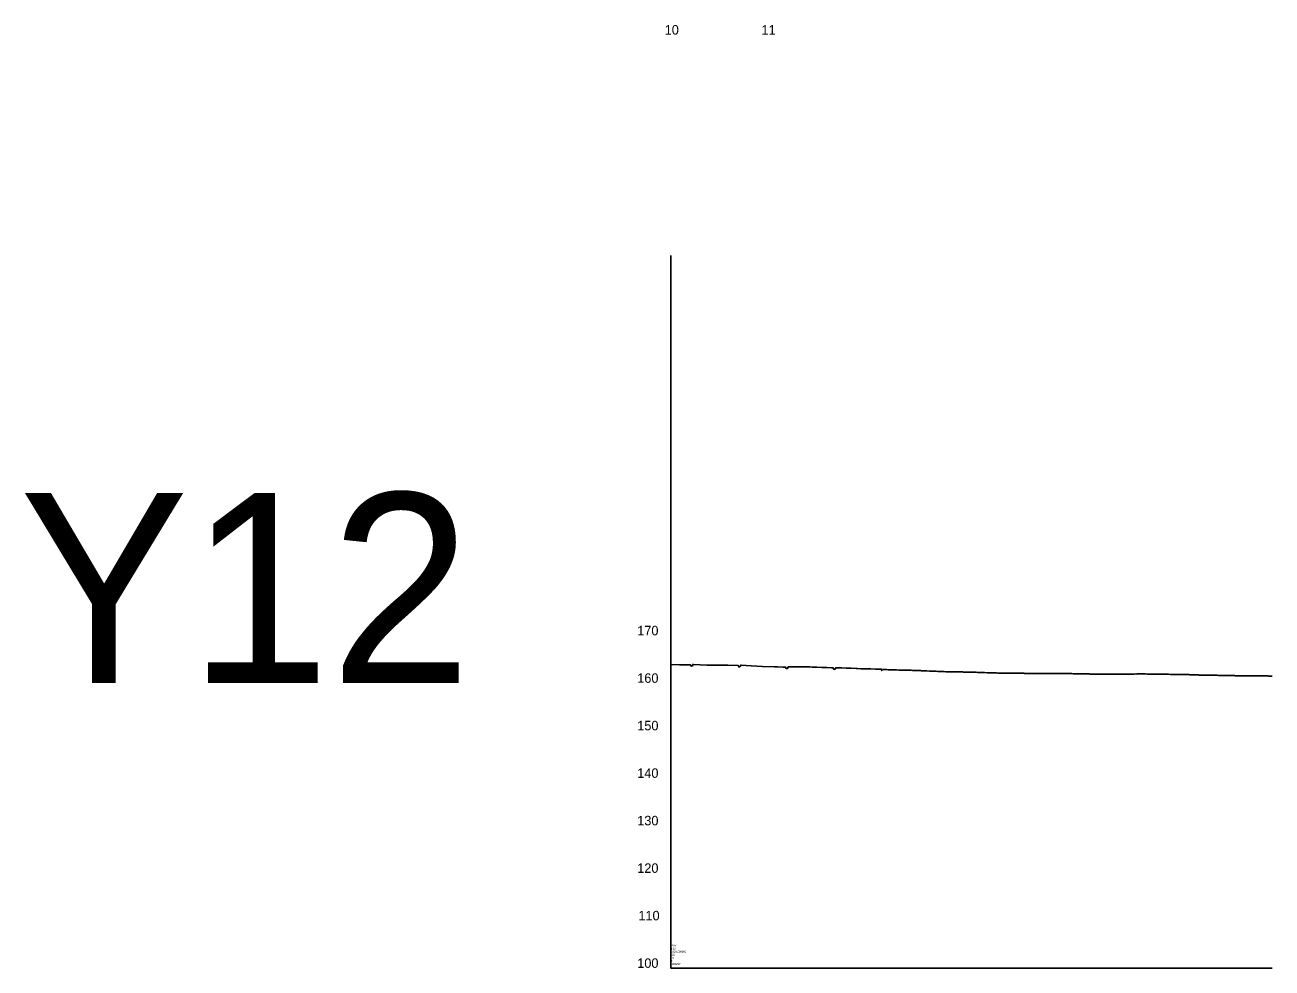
# Model space of a CAD drawing. Extents: x 1778432 to 1784301, y 601022 to 621789.
# Drawn here: x 1779463 to 1780776, y 606039 to 607032 of the extents above; entities that cross this region are included whole.
import ezdxf

# ---------------------------------------------------------------- set-up
doc = ezdxf.new("R2010")
doc.units = 0
for name, color, linetype in [('Exist Profile Cell', 7, 'Continuous'), ('Exist Vertical Profile Ground Line', 7, 'Continuous'), ('Exist Vertical Profile Horizontal Axis Label Major', 7, 'Continuous'), ('Exist Vertical Profile Vertical Axis Label', 7, 'Continuous'), ('Prop PFL Text', 7, 'Continuous')]:
    doc.layers.add(name, color=color, linetype=linetype)

msp = doc.modelspace()

# ---------------------------------------------------------------- linework, layer by layer
at = {"layer": 'Exist Profile Cell'}
for q in [(1780143, 606789.2), (1780775.8, 606039.2), (1780143, 606039.2)]:
    msp.add_line((1780143, 606039.2), q, dxfattribs=at)
at = {"layer": 'Exist Vertical Profile Ground Line'}
msp.add_lwpolyline([(1780143, 606358.7), (1780152.2, 606358.4), (1780163.8, 606358.3), (1780164.4, 606356.8), (1780165.2, 606357.2), (1780165.8, 606357.4), (1780166.4, 606359), (1780166.8, 606358.7), (1780180.8, 606358.1), (1780189.9, 606358), (1780202.9, 606358), (1780213.9, 606357.6), (1780214.5, 606356.1), (1780215.4, 606356.4), (1780215.9, 606356.5), (1780216.5, 606358), (1780216.9, 606358), (1780227.4, 606357.4), (1780239.5, 606356.7), (1780252.2, 606356.2), (1780255.6, 606356.1), (1780260.7, 606355.9), (1780263.8, 606355.9), (1780264.4, 606354.4), (1780265, 606354.4), (1780265.9, 606354.6), (1780266.5, 606356.1), (1780267, 606356.1), (1780271, 606356.1), (1780276.1, 606356.1), (1780277.8, 606356.1), (1780281.3, 606356.1), (1780286.4, 606356.1), (1780289.3, 606356.1), (1780291.6, 606356), (1780296.7, 606355.8), (1780301.9, 606355.6), (1780307, 606355.4), (1780312.2, 606355.2), (1780313.9, 606355.1), (1780314.5, 606353.6), (1780315.3, 606353.7), (1780315.9, 606353.8), (1780316.5, 606355.3), (1780316.9, 606355.3), (1780317.3, 606355.3), (1780322.5, 606355.1), (1780327.6, 606354.9), (1780329.5, 606354.9), (1780332.8, 606354.7), (1780337.9, 606354.5), (1780339.5, 606354.4), (1780343.1, 606354.3), (1780348.2, 606354.2), (1780352.5, 606354), (1780353.4, 606354), (1780358.5, 606353.9), (1780363.7, 606353.8), (1780364.4, 606353.8), (1780365, 606352.3), (1780366, 606353.5), (1780368.2, 606353.4), (1780368.9, 606353.4), (1780370, 606353.3), (1780371.8, 606353.2), (1780373, 606353.2), (1780374, 606353.1), (1780374.8, 606353.1), (1780377.3, 606353), (1780377.9, 606353), (1780379.1, 606353), (1780380.6, 606353), (1780382.8, 606352.9), (1780383.5, 606352.9), (1780384.5, 606352.9), (1780386.4, 606352.9), (1780387.7, 606352.8), (1780389.4, 606352.8), (1780391.6, 606352.7), (1780392.2, 606352.7), (1780392.6, 606352.7), (1780394.2, 606352.7), (1780394.6, 606352.7), (1780395.1, 606352.7), (1780396, 606352.6), (1780397.5, 606352.5), (1780398, 606352.5), (1780398.8, 606352.5), (1780399.7, 606352.5), (1780400.9, 606352.4), (1780401.5, 606352.4), (1780402.5, 606352.4), (1780403.8, 606352.4), (1780404.9, 606352.3), (1780405.7, 606352.3), (1780406.7, 606352.2), (1780407.4, 606352.2), (1780409.6, 606352.1), (1780410, 606352.1), (1780410.6, 606352.1), (1780412.6, 606351.9), (1780415.4, 606351.8), (1780416.1, 606351.7), (1780417.3, 606351.7), (1780418.3, 606351.7), (1780419.6, 606351.6), (1780420.3, 606351.6), (1780421.2, 606351.5), (1780422.3, 606351.5), (1780424, 606351.4), (1780425.5, 606351.3), (1780427.4, 606351.3), (1780429.8, 606351.2), (1780430.6, 606351.2), (1780432.4, 606351.1), (1780432.7, 606351.1), (1780434.4, 606351), (1780435.8, 606351), (1780436.2, 606351), (1780437.4, 606351), (1780438.1, 606351), (1780438.5, 606351), (1780439.9, 606350.9), (1780440.9, 606350.9), (1780441.3, 606350.9), (1780441.8, 606350.8), (1780442.4, 606350.9), (1780444.2, 606350.9), (1780445.4, 606350.8), (1780446.1, 606350.8), (1780447.5, 606350.8), (1780450, 606350.8), (1780450.9, 606350.7), (1780451.2, 606350.7), (1780452.9, 606350.7), (1780454.6, 606350.7), (1780455.7, 606350.6), (1780456.4, 606350.6), (1780457.7, 606350.6), (1780458.6, 606350.6), (1780460.1, 606350.6), (1780461.5, 606350.5), (1780462.7, 606350.5), (1780463.7, 606350.5), (1780464.3, 606350.5), (1780465.6, 606350.4), (1780466.7, 606350.3), (1780467.2, 606350.3), (1780467.9, 606350.3), (1780469.3, 606350.3), (1780470, 606350.2), (1780471.8, 606350.2), (1780473, 606350.1), (1780475.8, 606350), (1780477, 606350), (1780478.1, 606350), (1780478.6, 606350), (1780480.3, 606349.9), (1780481.5, 606349.9), (1780482.1, 606349.9), (1780483.3, 606349.8), (1780484.3, 606349.8), (1780485.6, 606349.8), (1780487.3, 606349.7), (1780488.5, 606349.7), (1780490.1, 606349.7), (1780492, 606349.6), (1780492.4, 606349.6), (1780493.2, 606349.6), (1780493.7, 606349.6), (1780495, 606349.6), (1780495.8, 606349.6), (1780497.6, 606349.6), (1780498.9, 606349.5), (1780500.5, 606349.5), (1780501.5, 606349.5), (1780502.7, 606349.5), (1780504.3, 606349.5), (1780506.1, 606349.4), (1780507.1, 606349.4), (1780507.9, 606349.4), (1780509.3, 606349.4), (1780510, 606349.4), (1780511.6, 606349.4), (1780513, 606349.4), (1780514.1, 606349.4), (1780514.6, 606349.4), (1780515.3, 606349.3), (1780515.7, 606349.3), (1780516.4, 606349.3), (1780517.6, 606349.3), (1780518.2, 606349.3), (1780518.8, 606349.3), (1780519.8, 606349.3), (1780520.8, 606349.3), (1780521.6, 606349.3), (1780523.3, 606349.3), (1780524.2, 606349.3), (1780525, 606349.3), (1780527, 606349.3), (1780528.4, 606349.3), (1780529.8, 606349.3), (1780530.4, 606349.3), (1780532.7, 606349.3), (1780533.6, 606349.3), (1780535.7, 606349.3), (1780537.4, 606349.3), (1780538.4, 606349.3), (1780538.8, 606349.3), (1780541.4, 606349.2), (1780542.5, 606349.2), (1780544.1, 606349.2), (1780545.2, 606349.2), (1780546.4, 606349.2), (1780546.9, 606349.2), (1780548.4, 606349.2), (1780549.5, 606349.1), (1780550, 606349.1), (1780550.5, 606349.1), (1780551.8, 606349.2), (1780552.5, 606349.2), (1780553.8, 606349.1), (1780555, 606349.1), (1780555.5, 606349.1), (1780556.3, 606349.1), (1780557.2, 606349.1), (1780557.8, 606349.1), (1780558.2, 606349.1), (1780559.6, 606349.1), (1780560.9, 606349.1), (1780561.3, 606349.1), (1780561.7, 606349.1), (1780562.6, 606349.1), (1780563.4, 606349.1), (1780563.8, 606349.1), (1780565.1, 606349.1), (1780566.3, 606349), (1780567.1, 606349), (1780568.1, 606349), (1780569, 606349), (1780569.4, 606349), (1780570.1, 606348.9), (1780571.8, 606348.9), (1780572.6, 606348.9), (1780573.6, 606348.9), (1780575, 606348.8), (1780575.6, 606348.8), (1780576.4, 606348.8), (1780577.4, 606348.8), (1780578, 606348.8), (1780579.2, 606348.8), (1780580.1, 606348.8), (1780580.6, 606348.7), (1780582, 606348.7), (1780583.5, 606348.7), (1780584.1, 606348.6), (1780584.7, 606348.6), (1780586.2, 606348.6), (1780587.7, 606348.6), (1780588.9, 606348.6), (1780589.6, 606348.6), (1780590.4, 606348.6), (1780591.4, 606348.6), (1780591.8, 606348.6), (1780593.1, 606348.5), (1780594.7, 606348.5), (1780595.4, 606348.5), (1780596, 606348.5), (1780596.9, 606348.5), (1780597.3, 606348.5), (1780599, 606348.5), (1780600.1, 606348.4), (1780600.8, 606348.4), (1780601.7, 606348.4), (1780602.9, 606348.4), (1780604, 606348.4), (1780605.5, 606348.4), (1780606.5, 606348.4), (1780607.5, 606348.4), (1780608.4, 606348.4), (1780609.4, 606348.4), (1780610.3, 606348.4), (1780610.7, 606348.4), (1780611.5, 606348.4), (1780613.2, 606348.4), (1780614, 606348.4), (1780615.6, 606348.4), (1780616.9, 606348.4), (1780617.8, 606348.5), (1780619, 606348.5), (1780619.5, 606348.5), (1780621.2, 606348.5), (1780621.5, 606348.5), (1780622.5, 606348.5), (1780623.6, 606348.5), (1780625.3, 606348.5), (1780627.8, 606348.6), (1780629.1, 606348.6), (1780630.7, 606348.6), (1780632.5, 606348.7), (1780632.8, 606348.7), (1780633.3, 606348.6), (1780634.3, 606348.7), (1780636, 606348.7), (1780636.7, 606348.7), (1780638.9, 606348.7), (1780639.3, 606348.7), (1780640.4, 606348.7), (1780641.2, 606348.7), (1780641.7, 606348.7), (1780642.6, 606348.7), (1780644.4, 606348.6), (1780645.9, 606348.6), (1780647.1, 606348.6), (1780647.9, 606348.6), (1780648.6, 606348.6), (1780649.9, 606348.6), (1780651.2, 606348.5), (1780651.7, 606348.5), (1780652.4, 606348.5), (1780653.4, 606348.5), (1780654.7, 606348.5), (1780655.4, 606348.5), (1780655.9, 606348.4), (1780657.7, 606348.4), (1780658.1, 606348.4), (1780659.2, 606348.4), (1780660.9, 606348.4), (1780662.9, 606348.4), (1780663.5, 606348.4), (1780664.6, 606348.4), (1780666.2, 606348.4), (1780667, 606348.4), (1780669, 606348.3), (1780670, 606348.3), (1780670.5, 606348.3), (1780671.5, 606348.3), (1780672, 606348.3), (1780673.1, 606348.3), (1780674.5, 606348.3), (1780676.2, 606348.2), (1780677.4, 606348.2), (1780678.3, 606348.2), (1780679.4, 606348.2), (1780679.9, 606348.2), (1780680.4, 606348.2), (1780681.8, 606348.1), (1780682.7, 606348.1), (1780683.7, 606348.1), (1780685.6, 606348.1), (1780687.4, 606348), (1780688.1, 606348), (1780689.3, 606347.9), (1780690.7, 606347.9), (1780691.3, 606347.9), (1780692, 606347.9), (1780693, 606347.9), (1780693.5, 606347.8), (1780694.5, 606347.8), (1780695.9, 606347.7), (1780696.8, 606347.7), (1780698.4, 606347.7), (1780699, 606347.6), (1780699.4, 606347.6), (1780700.6, 606347.6), (1780700.9, 606347.6), (1780702.1, 606347.6), (1780704.5, 606347.5), (1780704.9, 606347.5), (1780707.4, 606347.4), (1780708.1, 606347.4), (1780708.9, 606347.4), (1780709.9, 606347.4), (1780710.8, 606347.4), (1780711.4, 606347.4), (1780711.9, 606347.4), (1780712.5, 606347.4), (1780714, 606347.3), (1780715, 606347.3), (1780715.6, 606347.3), (1780716.3, 606347.3), (1780718, 606347.3), (1780719.4, 606347.2), (1780720, 606347.2), (1780721.6, 606347.2), (1780723.2, 606347.1), (1780723.8, 606347.1), (1780724.6, 606347.1), (1780725.6, 606347.1), (1780726, 606347.1), (1780726.9, 606347.1), (1780728, 606347), (1780728.7, 606347), (1780730.2, 606347), (1780730.7, 606347), (1780731.4, 606347), (1780733.2, 606347), (1780733.7, 606347), (1780734.4, 606347), (1780735.6, 606347), (1780736.4, 606347), (1780737.5, 606346.9), (1780738.3, 606346.9), (1780740.4, 606346.9), (1780741, 606346.9), (1780742, 606346.9), (1780742.9, 606346.9), (1780744.9, 606346.9), (1780745.7, 606346.9), (1780748, 606346.8), (1780748.4, 606346.8), (1780749.5, 606346.8), (1780750.5, 606346.8), (1780753.3, 606346.7), (1780753.9, 606346.7), (1780755.5, 606346.7), (1780757, 606346.7), (1780758.2, 606346.7), (1780760.8, 606346.7), (1780761.9, 606346.7), (1780764.6, 606346.7), (1780765.3, 606346.7), (1780766.5, 606346.7), (1780767.1, 606346.7), (1780768.3, 606346.6), (1780769.1, 606346.6), (1780769.5, 606346.6), (1780771.6, 606346.6), (1780772.1, 606346.5), (1780772.7, 606346.5), (1780773, 606346.5), (1780773.5, 606346.5), (1780774.9, 606346.5), (1780775.8, 606346.5)], dxfattribs=at)

# ---------------------------------------------------------------- texts
at = {"layer": 'Exist Profile Cell'}
for s, p in [('Y12', (1780143, 606058.7)), ('RDY', (1780143, 606061.9)), ('2', (1780143, 606045.7)), ('1000.000000', (1780143, 606055.4)), ('100', (1780143, 606052.2)), ('10', (1780143, 606048.9)), ('NOGAP', (1780143, 606042.4))]:
    msp.add_text(s, height=2, dxfattribs=at).set_placement(p)
at = {"layer": 'Exist Vertical Profile Horizontal Axis Label Major'}
for s, p in [('10', (1780136.5, 607021.7)), ('11', (1780238.4, 607021.7))]:
    msp.add_text(s, height=10, dxfattribs=at).set_placement(p)
at = {"layer": 'Exist Vertical Profile Vertical Axis Label'}
for s, p in [('170', (1780107.6, 606389.4)), ('160', (1780107.6, 606339.4)), ('150', (1780107.6, 606289.4)), ('140', (1780107.6, 606239.4)), ('130', (1780107.6, 606189.4)), ('120', (1780107.6, 606139.4)), ('110', (1780108.8, 606089.4)), ('100', (1780107.6, 606039.4))]:
    msp.add_text(s, height=10, dxfattribs=at).set_placement(p)
at = {"layer": 'Prop PFL Text'}
msp.add_text('Y12', height=200, dxfattribs=at).set_placement((1779457.1, 606339.2))

doc.saveas('drawing.dxf')
